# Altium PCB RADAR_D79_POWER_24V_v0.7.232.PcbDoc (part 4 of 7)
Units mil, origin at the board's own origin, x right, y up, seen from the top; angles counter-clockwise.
Board outline 3110.24 x 3110.24 mil, 8 copper layers (Top Layer, GND1, SIG1, PWR1, PWR2, SIG2, GND2, Bottom Layer), stack 55.2 mil thick; 304 components, 269 nets, 1408 pads, 1367 vias.
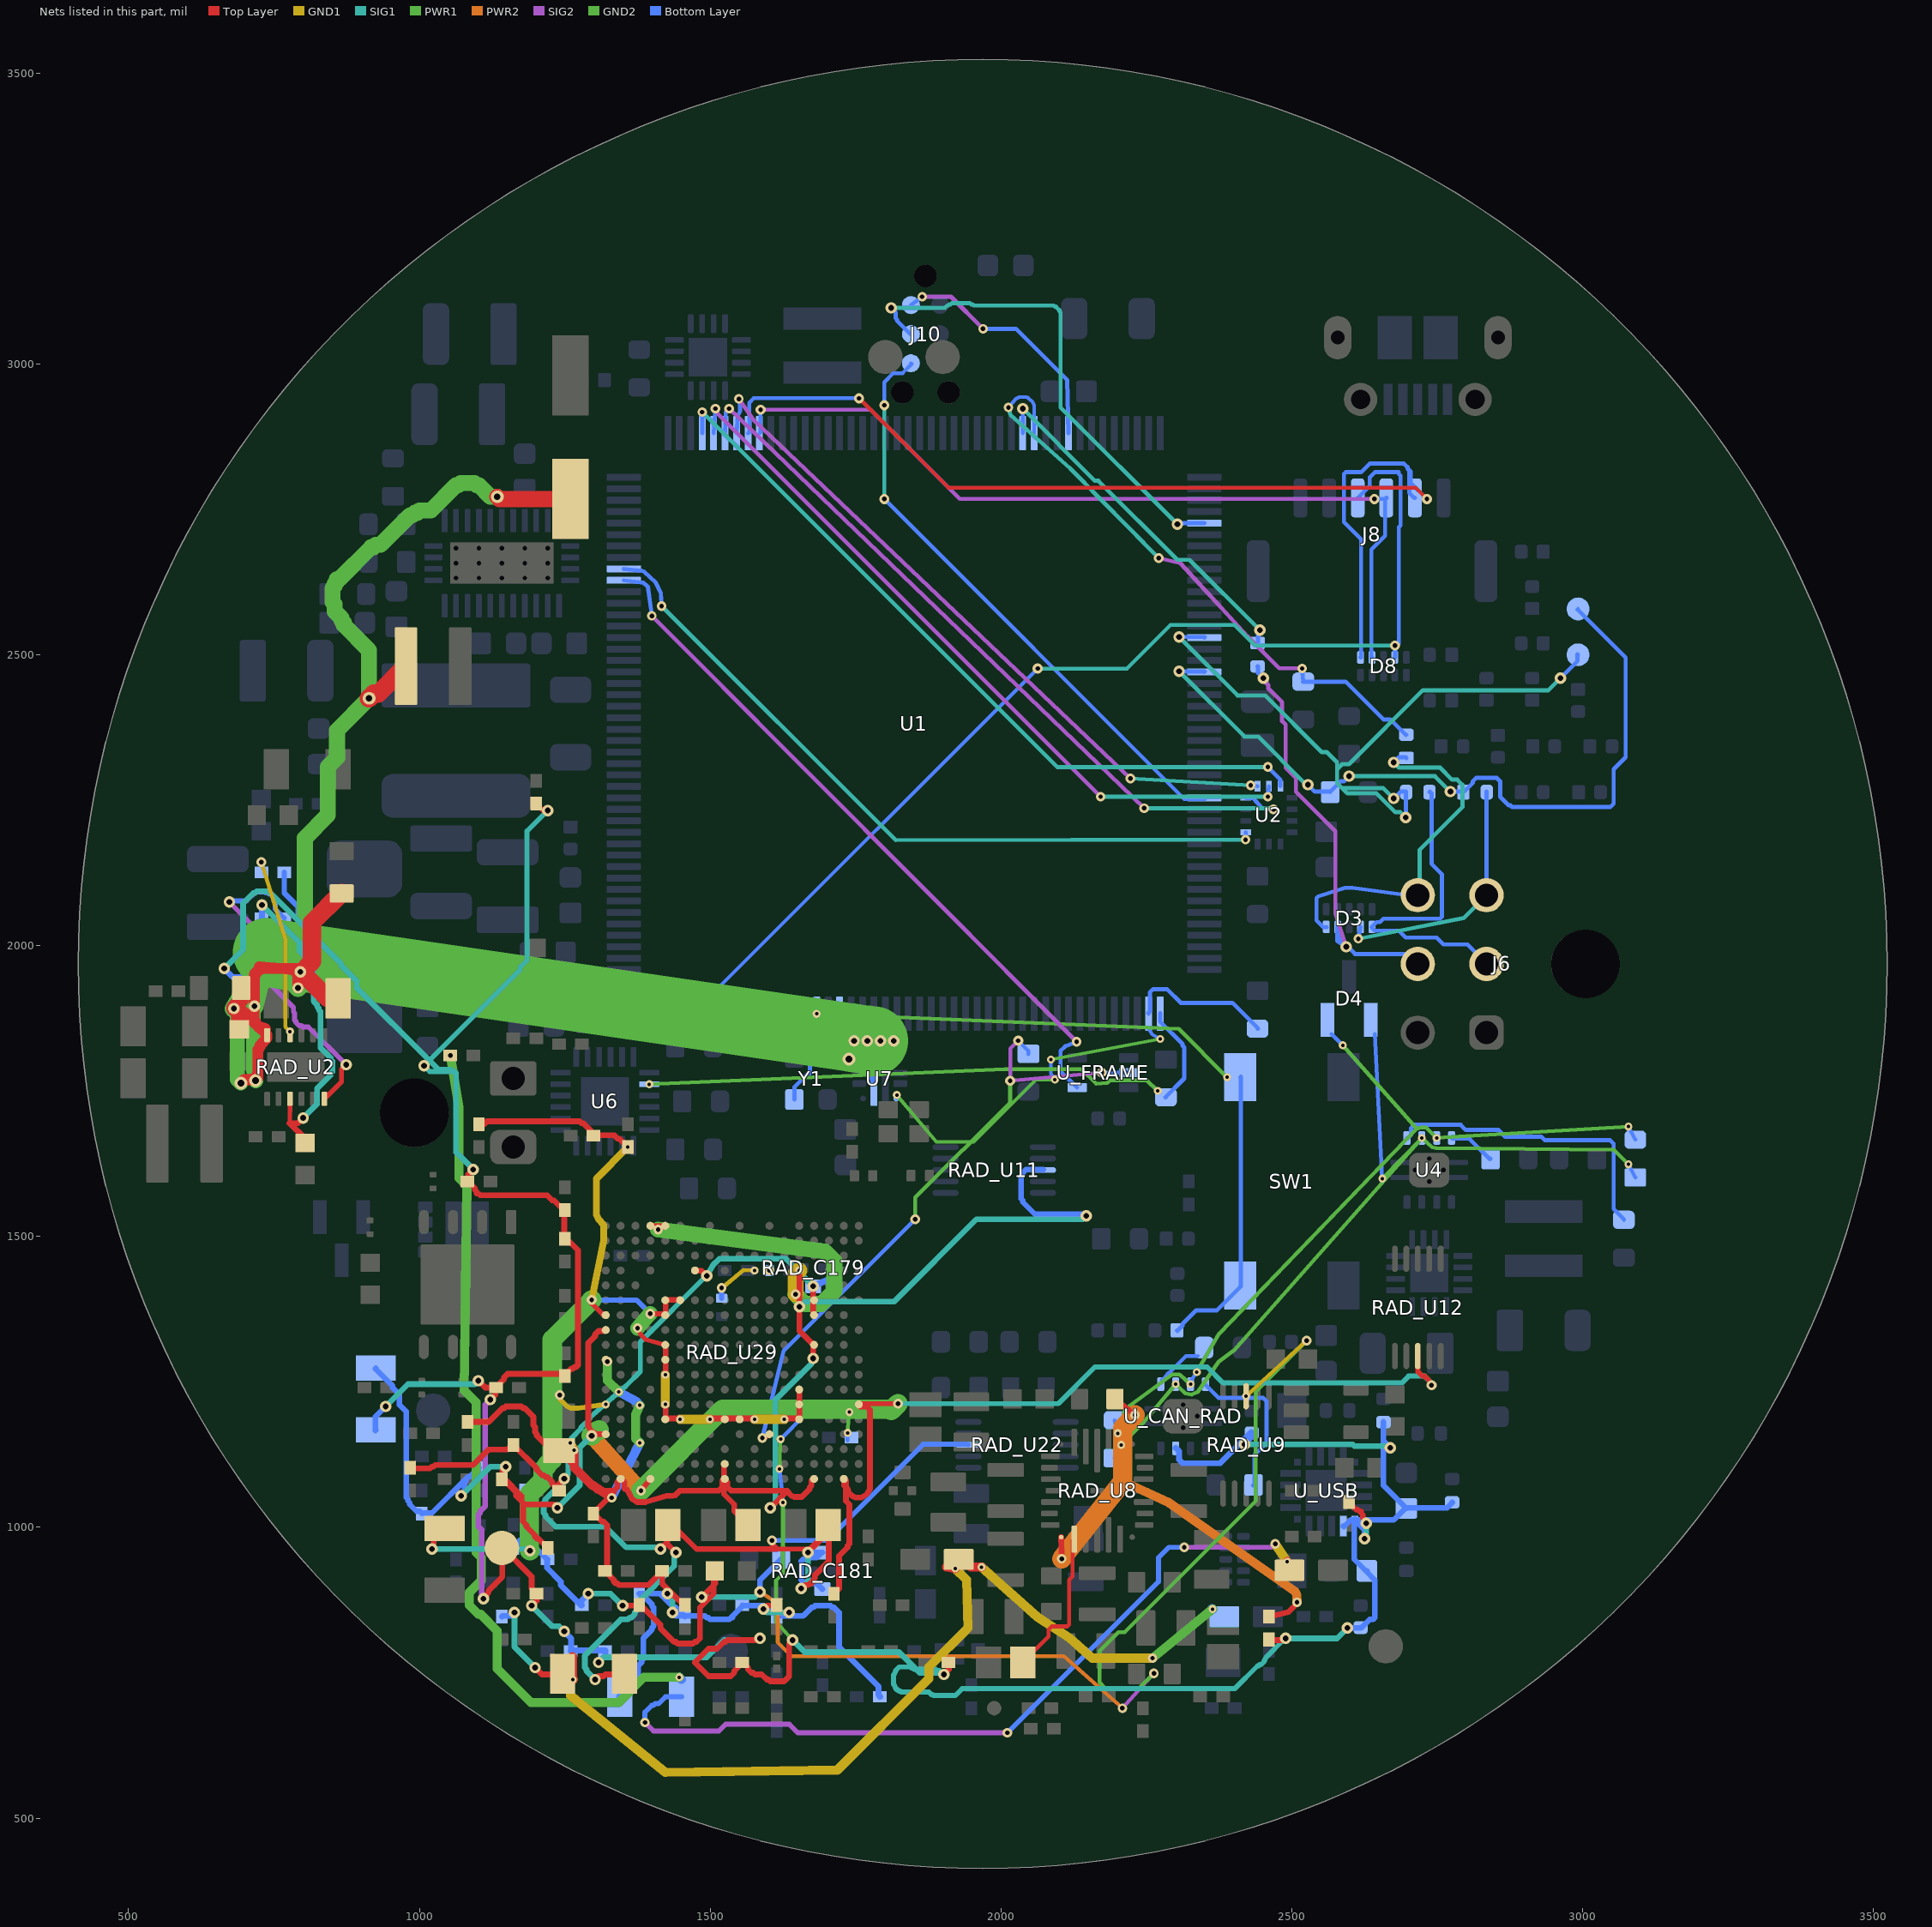
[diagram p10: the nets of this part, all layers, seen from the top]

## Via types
v1: diameter 13.77, hole 5.9, Top Layer to GND1, tented both sides, 393 vias
v2: diameter 16.54, hole 7.87, Top Layer to Bottom Layer, tented both sides, 129 vias
v3: diameter 19.68, hole 9.84, Top Layer to Bottom Layer, tented both sides, 126 vias
v4: diameter 13.77/13.77 (per signal layer), hole 5.9, Top Layer to GND1, tented both sides, 120 vias
v5: diameter 13.77, hole 5.9, Top Layer to GND1, tented top, 104 vias
v6: diameter 13.78, hole 5.91, Top Layer to GND1, tented both sides, 75 vias
v7: diameter 19.68, hole 9.84, Top Layer to Bottom Layer, 74 vias
v8: diameter 17.32, hole 7.87, Top Layer to Bottom Layer, tented both sides, 71 vias
v9: diameter 13.78, hole 5.91, GND2 to Bottom Layer, tented both sides, 64 vias
v10: diameter 13.78, hole 5.91, Top Layer to GND1, tented bottom, 39 vias
v11: diameter 13.78, hole 5.91, GND2 to Bottom Layer, tented top, 38 vias
v12: diameter 13.78, hole 5.91, Top Layer to GND1, 26 vias
v13: diameter 16.54, hole 7.87, GND2 to Bottom Layer, tented both sides, 22 vias
v14: diameter 16.54, hole 7.87, Top Layer to Bottom Layer, 19 vias
v15: diameter 22.05, hole 11.81, Top Layer to Bottom Layer, tented both sides, 17 vias
v16: diameter 13.78, hole 5.91, GND2 to Bottom Layer, 9 vias
v17: diameter 18.11, hole 9.06, Top Layer to Bottom Layer, 7 vias
v18: diameter 22.83, hole 11.81, Top Layer to Bottom Layer, 6 vias
v19: diameter 22.05, hole 11.81, Top Layer to Bottom Layer, 6 vias
v20: diameter 22.83, hole 11.81, Top Layer to Bottom Layer, tented both sides, 5 vias
v21: diameter 19.68, hole 7.87, Top Layer to Bottom Layer, 3 vias
v22: diameter 17.32, hole 8.66, Top Layer to Bottom Layer, 3 vias
v23: diameter 20.47, hole 9.84, Top Layer to Bottom Layer, 3 vias
v24: diameter 17.72, hole 9.84, Top Layer to Bottom Layer, tented both sides, 2 vias
v25: diameter 22.05, hole 11.02, Top Layer to Bottom Layer, 2 vias
v26: diameter 19.68, hole 11.81, Top Layer to Bottom Layer, 2 vias
v27: diameter 18, hole 9.84, Top Layer to Bottom Layer, tented both sides, 1 vias
v28: diameter 18.11, hole 9.06, Top Layer to Bottom Layer, tented both sides, 1 vias

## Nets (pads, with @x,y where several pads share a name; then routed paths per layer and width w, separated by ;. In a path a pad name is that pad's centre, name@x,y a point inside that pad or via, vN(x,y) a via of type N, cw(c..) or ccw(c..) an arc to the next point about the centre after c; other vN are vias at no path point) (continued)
GNSS_PPS: D8.4 J8.4 U1.40 | length 1929.4
  SIG1 w6.69: v8(2062.99,2476.38) 2216.54,2476.38 2291.34,2551.18 2401.57,2551.18 2437.01,2515.75 v8(2677.17,2515.75)
  Bottom Layer w6.69: U1.40@1505.91,1882.87 1507.87,1881.89 1507.87,1921.26 v8(2062.99,2476.38) ; D8.4@2677.17,2495.47 2677.17,2496.06 v8(2677.17,2515.75)
  Bottom Layer w7.09: J8.4@2613.19,2769.68 2633.86,2790.35 2633.86,2805.12 2642.72,2813.98 2684.06,2813.98 2684.06,2811.02 2687.01,2808.07 2687.01,2722.44 2684.06,2719.49 2684.06,2518.7 2678.15,2512.8 2678.15,2495.08 D8.4@2677.17,2495.47
GNSS_RX_EXT: D8.1 J8.2 U1.96 | length 1867.5
  Top Layer w6.69: v8(1755.91,2940.94) 1909.45,2787.4 2712.6,2787.4 v8(2732.28,2767.72)
  Bottom Layer w6.69: U1.96@1564.96,2880.91 1566.93,2881.89 1566.93,2933.07 1574.8,2940.94 v8(1755.91,2940.94) ; 2698.82,2819.88 2700.79,2818.9 2704.72,2814.96 2704.72,2795.28 v8(2732.28,2767.72)
  Bottom Layer w7.09: D8.1@2618.11,2495.47 2619.09,2495.08 2619.09,2698.82 2589.57,2728.35 2589.57,2811.02 2592.52,2813.98 2619.09,2813.98 2633.86,2828.74 2692.91,2828.74 2698.82,2822.83 2698.82,2819.88 2701.77,2816.93 2701.77,2778.54 2710.63,2769.68 J8.2@2711.61,2769.68
GNSS_TX_EXT: D8.2 J8.3 U1.97 | length 1469.8
  SIG2 w6.69: v8(1586.61,2921.26) 1775.59,2921.26 1929.13,2767.72 v8(2641.73,2767.72)
  Bottom Layer w6.69: U1.97@1584.65,2880.91 1586.61,2881.89 v8(1586.61,2921.26) ; v8(2641.73,2767.72) 2661.42,2767.72 J8.3@2662.4,2769.68
  Bottom Layer w7.09: D8.2@2637.8,2495.47 2636.81,2495.08 2636.81,2681.1 2660.43,2704.72 2660.43,2766.73 2661.42,2767.72 2663.39,2769.68 J8.3@2662.4,2769.68
HOST_UART1_RX: R600.2 R602.2 TP2.1 U1.150 | length 1331.2
  SIG1 w7.09: v3(2306.1,2471.46) 2418.31,2359.25 2441.93,2359.25 2521.65,2279.53 2524.61,2279.53 v7(2527.56,2276.57) ; v3(2598.43,2291.34) 2746.06,2291.34 v3(2772.64,2264.76)
  Bottom Layer w7.09: v3(2306.1,2471.46) 2350.39,2471.46 U1.150@2349.41,2470.47 ; v7(2527.56,2276.57) 2539.37,2264.76 R600.2@2565.94,2264.76 ; R600.2@2565.94,2263.78 R600.2@2565.94,2264.76 ; v3(2598.43,2291.34) 2589.57,2282.48 2583.66,2282.48 R600.2@2565.94,2264.76 ; v3(2772.64,2264.76) R602.2@2796.26,2264.76 ; R602.2@2794.88,2263.78 R602.2@2796.26,2264.76 ; TP2.1@2992.13,2578.74 2991.14,2577.76 3073.82,2495.08 3073.82,2323.82 3053.15,2303.15 3053.15,2244.09 3047.24,2238.19 2878.94,2238.19 2875.98,2241.14 2873.03,2241.14 2858.27,2255.91 2858.27,2282.48 2852.36,2288.39 2816.93,2288.39 2811.02,2282.48 2811.02,2279.53 R602.2@2796.26,2264.76
HOST_UART1_RX_EXT: D3.2 J6.3 R602.1 | length 440.1
  SIG1 w7.09: v2(2614.17,2011.81) 2795.28,2047.24 J6.3@2834.65,2086.61
  Bottom Layer w7.09: v2(2614.17,2011.81) D3.2@2618.11,2032.09 ; J6.3@2834.65,2086.61 2834.65,2087.6 2834.65,2264.76 R602.1@2835.04,2263.78
HOST_UART1_TX: R601.2 TP1.1 U1.147 | length 1255.2
  SIG1 w7.09: v3(2306.1,2530.51) 2406.5,2430.12 2453.74,2430.12 2551.18,2332.68 2560.04,2332.68 2577.76,2314.96 2577.76,2303.15 ; v7(2675.2,2252.95) 2657.48,2270.67 2586.61,2270.67 ; v7(2695.87,2220.47) 2687.01,2229.33 2678.15,2229.33 2645.67,2261.81 2595.47,2261.81 2586.61,2270.67 ; v7(2961.61,2459.65) 2940.94,2438.98 2725.39,2438.98 2598.43,2312.01 2586.61,2312.01 2577.76,2303.15 ; 2577.76,2303.15 2577.76,2279.53 2586.61,2270.67
  Bottom Layer w7.09: v3(2306.1,2530.51) 2350.39,2530.51 U1.147@2349.41,2529.53 ; v7(2675.2,2252.95) 2687.01,2264.76 R601.2@2695.87,2264.76 ; v7(2695.87,2220.47) R601.2@2695.87,2264.76 ; R601.2@2696.46,2263.78 R601.2@2695.87,2264.76 ; v7(2961.61,2459.65) 2991.14,2489.17 2991.14,2500.98 TP1.1@2992.13,2500
HOST_UART1_TX_EXT: D3.1 J6.2 R601.1 | length 579.3
  Bottom Layer w7.09: D3.1@2637.8,2032.09 D3.1@2636.81,2031.5 ; R601.1@2736.61,2263.78 2737.2,2264.76 2740.16,2261.81 2740.16,2140.75 2757.87,2123.03 2757.87,2049.21 2754.92,2046.26 2657.48,2046.26 2651.57,2040.35 2645.67,2040.35 2637.6,2032.28 D3.1@2636.81,2031.5 ; J6.2@2834.65,1968.5 2834.65,1969.49 2802.17,2001.97 2760.83,2001.97 2749.02,2013.78 2695.87,2013.78 2684.06,2025.59 2642.72,2025.59 D3.1@2636.81,2031.5
HOST_UART2_RX: R604.2 R605.2 U1.121 | length 1039.6
  SIG1 w7.09: v2(2012.8,2925.2) 2016.14,2912.6 2118.9,2820.47 v2(2271.26,2666.34)
  SIG2 w7.09: v2(2271.26,2666.34) 2308.46,2657.48 2423.62,2531.69 2478.54,2476.77 v2(2517.72,2476.38)
  Bottom Layer w6.3: v2(2012.8,2925.2) 2025.59,2939.96 2031.5,2942.91 2043.31,2942.91 2046.26,2941.93 2054.13,2935.04 2057.09,2929.13 U1.121@2057.09,2880.91
  Bottom Layer w7.09: v2(2517.72,2476.38) R605.2@2519.68,2453.74 ; R604.2@2696.85,2362.6 2695.87,2362.2 2669.29,2388.78 2657.48,2388.78 2592.52,2453.74 R605.2@2519.68,2453.74 ; R605.2@2519.68,2453.74 2518.7,2453.74 R605.2@2519.68,2453.74
HOST_UART2_RX_EXT: D3.5 J6.6 R604.1 | length 624.9
  SIG1 w7.09: v3(2675.2,2314.96) 2684.06,2306.1 2754.92,2306.1 2775.59,2285.43 2784.45,2285.43 2793.31,2276.57 2793.31,2238.19 2719.49,2164.37 2719.49,2090.55 2716.54,2087.6 J6.6@2716.54,2086.61
  Bottom Layer w7.09: D3.5@2559.06,2032.09 2560.04,2031.5 2554.13,2031.5 2542.32,2043.31 2542.32,2081.69 2545.28,2084.65 2591.54,2099.41 2604.33,2099.41 2713.58,2084.65 2716.54,2087.6 J6.6@2716.54,2086.61 ; v3(2675.2,2314.96) 2684.06,2323.82 2695.87,2323.82 R604.1@2696.85,2322.44
HOST_UART2_TX: R603.2 U1.120 | length 634.1
  SIG1 w7.09: v3(2037.4,2923.23) 2161.42,2799.21 2167.32,2799.21 2303.15,2663.39 2323.82,2663.39 v7(2444.88,2542.32)
  Bottom Layer w7.09: U1.120@2037.4,2880.91 2037.4,2881.89 v3(2037.4,2923.23) ; R603.2@2440.94,2520.08 2441.93,2518.7 2441.93,2539.37 v7(2444.88,2542.32)
HOST_UART2_TX_EXT: D3.4 J6.5 R603.1 | length 758.4
  SIG2 w7.09: v7(2450.79,2459.65) 2456.69,2453.74 2456.69,2450.79 2459.65,2447.83 2459.65,2441.93 2483.27,2418.31 2483.27,2385.83 2489.17,2379.92 2489.17,2306.1 2506.89,2288.39 2506.89,2264.76 2574.8,2196.85 2574.8,2055.12 v7(2593.5,1998.03)
  Bottom Layer w7.09: R603.1@2440.94,2479.92 2441.93,2480.32 2441.93,2468.5 v7(2450.79,2459.65) ; D3.4@2578.74,2032.09 D3.4@2577.76,2031.5 ; v7(2593.5,1998.03) 2577.76,2007.87 D3.4@2577.76,2031.5 ; J6.5@2716.54,1968.5 2715.94,1969.09 2699.41,1985.63 2608.46,1985.63 2580.91,2013.19 2580.71,2013.78 2580.71,2028.54 D3.4@2577.76,2031.5
IMU_DRDY: U1.80 U2.4 | length 1289
  SIG1 w7.09: v2(1416.34,2583.66) 1818.9,2181.1 v2(2420.28,2182.09)
  Bottom Layer w7.09: U1.80@1351.38,2647.64 1381.89,2644.68 1386.81,2642.72 1406.5,2624.02 1415.35,2605.32 v2(1416.34,2583.66) ; v2(2420.28,2182.09) U2.4@2420.77,2194.88
IMU_MISO: U1.94 U2.1 | length 1314.4
  SIG1 w7.09: v2(2246.06,2236.22) 2466.54,2236.22 v2(2468.5,2234.25)
  SIG2 w7.09: v2(1532.48,2923.23) v2(2246.06,2236.22)
  Bottom Layer w7.09: U1.94@1525.59,2880.91 1526.57,2917.32 v2(1532.48,2923.23) ; U2.1@2420.77,2253.94 2433.07,2253.94 2448.82,2236.22 v2(2468.5,2234.25)
IMU_MOSI: U1.95 U2.14 | length 1218.4
  SIG1 w7.09: v2(2222.44,2287.4) v2(2429.13,2275.59)
  SIG2 w7.09: v2(1549.21,2939.96) 1574.8,2903.54 v2(2222.44,2287.4)
  Bottom Layer w7.09: U1.95@1545.28,2880.91 1547.24,2911.42 1550.2,2915.35 1551.18,2918.31 1551.18,2937.99 v2(1549.21,2939.96) ; v2(2429.13,2275.59) U2.14@2440.94,2274.11
IMU_NSS: U1.92 U2.12 | length 1303.6
  SIG1 w7.09: v2(1486.22,2917.32) 2096.46,2307.09 v2(2458.66,2307.09)
  Bottom Layer w7.09: U1.92@1486.22,2880.91 v2(1486.22,2917.32) ; v2(2458.66,2307.09) 2480.32,2285.43 U2.12@2480.31,2274.11
IMU_SCK: U1.93 U2.13 | length 1289
  SIG1 w7.09: v2(2171.26,2255.91) v2(2458.66,2255.91)
  SIG2 w7.09: v2(1508.86,2923.23) 1513.78,2913.39 v2(2171.26,2255.91)
  Bottom Layer w7.09: U1.93@1505.91,2880.91 v2(1508.86,2923.23) ; v2(2458.66,2255.91) U2.13@2460.63,2274.11
MCU_HSE_25M: U1.29 Y1.3 | length 204.3
  Bottom Layer w7.09: Y1.3@1644.68,1735.24 1644.68,1756.89 1668.31,1780.51 1671.26,1780.51 1671.26,1830.71 1683.07,1842.52 1718.5,1842.52 1718.5,1845.47 1721.46,1848.43 1721.46,1883.86 U1.29@1722.44,1882.87
NRST: C115.1 SW1.1 U1.31 | length 1247.5
  GND2 w6.69: v11(1683.07,1882.87) 2305.51,1856.69 v11(2388.58,1773.62)
  Bottom Layer w7.09: C115.1@2302.36,1338.58 2303.15,1337.6 2312.01,1346.46 2312.01,1349.41 2335.63,1373.03 2371.06,1373.03 SW1.1@2412.4,1414.37 ; SW1.1@2411.42,1415.35 SW1.1@2412.4,1414.37 ; SW1.1@2411.42,1773.62 2412.4,1774.61 SW1.1@2412.4,1414.37
RAD_CAN_SHDN: R_CAN_SHDN.1 U_CAN_RAD.5 | length 81.7
  Bottom Layer w6.3: U_CAN_RAD.5@2276.18,1253.35 2276.08,1253.69 2277.31,1253.69 2285.93,1262.3 2285.93,1263.53 2287.16,1263.53 2287.16,1264.76 2288.39,1264.76 2288.39,1265.99 2289.62,1265.99 2317.91,1294.29 2337.6,1294.29 R_CAN_SHDN.1@2338.19,1294.88
RAD_CAN_STB: R_CAN_STB.1 U_CAN_RAD.8 | length 275.4
  Bottom Layer w7.09: U_CAN_RAD.8@2351.38,1246.06 2350.39,1246.06 2350.89,1245.57 2374.02,1222.44 2450.79,1222.44 2456.69,1216.54 2456.69,1145.67 2436.02,1125 2436.02,1074.8 R_CAN_STB.1@2434.06,1072.83 ; R_CAN_STB.1@2434.06,1072.83 2433.07,1071.85 R_CAN_STB.1@2434.06,1072.83
RAD_FRAME_RAW: R_FRAME_PD.1 RAD_U29.G15 U_FRAME.2 | length 1106.1
  Top Layer w7.09: v2(1589.57,1153.54) 1590.55,1154.53 1595.47,1154.53 1601.38,1160.43 RAD_U29.G15@1601.8,1160.03
  PWR1 w7.09: v2(1852.36,1529.53) 1852.36,1566.93 2015.75,1730.32 v8(2015.75,1767.72)
  SIG2 w6.69: v8(2015.75,1767.72) 2015.75,1822.83 v8(2029.53,1836.61)
  SIG2 w7.09: v8(2015.75,1767.72) v2(2173.03,1781.69)
  Bottom Layer w6.69: v8(2029.53,1836.61) 2047.24,1818.9 R_FRAME_PD.1@2047.24,1813.98 ; R_FRAME_PD.1@2047.24,1813.98 2047.24,1812.99 R_FRAME_PD.1@2047.24,1813.98
  Bottom Layer w7.09: v2(1589.57,1153.54) 1625.98,1303.15 v2(1852.36,1529.53) ; v2(2173.03,1781.69) U_FRAME.2@2219.49,1781.5
RADAR_12V: RAD_C99.1 RAD_C101.1 RAD_C118.2 RAD_C173.2 RAD_C195.1 RAD_L5.2 RAD_R7.1 RAD_U2.12 U7.6 | length 4553.2
  Top Layer w12.2: v3@716.54,1897.64 v3(716.54,1895.67) 716.54,1872.05 716.54,1871.06 716.54,1870.08 717.88,1868.73 718.5,1868.11 727.36,1859.25 730.32,1856.3 740.16,1846.46 738.18,1846.43 RAD_U2.12@737.32,1846.42
  Top Layer w18.9: v3(681.1,1891.73) 682.09,1890.75 684.06,1890.75 692.91,1890.75 717.52,1866.14 ; v15(692.91,1763.78) 698.82,1769.68 710.63,1769.68 712.6,1770.47 716.54,1770.47 720.47,1775.59 721.42,1779.53 722.44,1781.5 ; 716.54,1871.06 715.55,1872.05 715.55,1946.85 716.54,1947.83 716.54,1950.79 717.52,1951.77 717.52,1952.76 723.43,1958.66 724.23,1958.66 ; 716.54,1872.05 717.56,1870.08 717.88,1868.73 ; v3@716.54,1897.64 716.54,1946.85 717.56,1948.82 718.5,1952.76 722.44,1956.69 724.08,1957.03 724.23,1958.66 ; v15(718.5,1767.72) 722.44,1771.65 722.44,1781.5 ; RAD_U2.12@734.84,1856.69 RAD_U2.12@735.24,1856.3 ; v3(791.34,1927.17) 791.34,1946.85 790.55,1948.82 790.55,1952.76 785.43,1956.69 783.8,1957.03 781.83,1959 761.89,1960.63 ; v3(795.28,1954.72) 789.37,1960.63 761.89,1960.63 ; 717.52,1866.14 723.43,1860.24 ; 717.52,1866.14 717.52,1867.13 716.54,1868.11 716.54,1870.08 717.88,1868.73 ; 717.88,1868.73 718.5,1868.11 718.5,1866.14 ; 717.88,1868.73 718.5,1866.14 ; 718.5,1866.14 724.25,1860.24 ; 722.44,1781.5 722.44,1820.87 724.41,1822.83 724.41,1824.8 726.38,1826.77 726.38,1828.74 737.32,1840.91 737.32,1846.06 737.32,1846.42 737.32,1846.82 728.09,1856.3 ; 723.43,1860.24 727.36,1856.3 728.09,1856.3 ; 723.43,1860.24 724.25,1860.24 ; 724.25,1860.24 728.09,1856.3 ; 724.25,1860.24 724.41,1860.24 725.39,1859.25 727.36,1859.25 728.35,1859.25 729.33,1858.27 733.27,1858.27 RAD_U2.12@735.24,1856.3 ; 724.23,1958.66 724.71,1963.68 761.89,1960.63 ; 724.23,1958.66 724.41,1958.66 725.39,1959.65 728.35,1959.65 729.33,1960.63 761.89,1960.63 ; 728.09,1856.3 730.32,1856.3 RAD_U2.12@735.24,1856.3
  Top Layer w25.59: v3(681.1,1891.73) v3@681.1,1893.7 ; RAD_C195.1@690.2,1856.13 688.98,1854.33 688.98,1885.83 684.06,1890.75 v3@681.1,1893.7 ; RAD_C118.2@693.77,1927.05 692.91,1925.2 692.91,1905.51 v3@681.1,1893.7
  Top Layer w27.56: v25(1133.86,2771.65) 1137.8,2767.72 RAD_C99.1@1259.84,2767.72
  Top Layer w31.5: v3(795.28,1954.72) v3@796.18,1952.76 ; RAD_C101.1@860.24,1909.45 842.52,1909.45 799.21,1952.76 v3@796.18,1952.76 ; RAD_C173.2@866.14,2089.57 866.14,2090.55 814.96,2039.37 814.96,1972.44 796.73,1953.33 v3@796.18,1952.76 ; v25(913.39,2425.2) 921.26,2433.07 929.13,2433.07 976.38,2480.32 RAD_L5.2@976.97,2480.32
  PWR1 w25.59: v3(681.1,1891.73) 683.07,1889.76 683.07,1885.83 687.01,1881.89 687.01,1769.68 v15(692.91,1763.78) ; v3(716.54,1895.67) 714.57,1893.7 714.57,1785.43 716.54,1783.46 716.54,1777.56 718.5,1775.59 v15(718.5,1767.72) ; v19(1738.19,1805.12) 1738.19,1826.77 1747.64,1836.22 1748.03,1836.61 v3(1747.24,1836.22)
  PWR1 w27.56: v3@795.28,1952.76 v3(795.28,1954.72) 795.28,1968.5 803.15,1976.38 803.15,1978.73 803.15,2185.04 842.52,2224.41 842.52,2307.09 858.27,2322.83 858.27,2370.08 v25(913.39,2425.2) 913.39,2507.87 870.08,2551.18 870.08,2555.12 866.14,2559.06 866.14,2562.99 854.33,2574.8 854.33,2586.61 850.39,2590.55 850.39,2614.17 854.33,2618.11 854.33,2622.05 858.27,2625.98 858.27,2629.92 862.2,2629.92 917.32,2685.04 921.26,2685.04 925.2,2688.98 933.07,2688.98 984.25,2740.16 988.19,2740.16 992.13,2744.09 996.06,2744.09 1000,2748.03 1019.68,2748.03 1062.99,2791.34 1066.93,2791.34 1070.87,2795.28 1094.49,2795.28 1098.43,2791.34 1102.36,2791.34 1122.05,2771.65 v25(1133.86,2771.65)
  PWR1 w31.5: v3(681.1,1891.73) 738.19,1988.19 ; v3(716.54,1895.67) 738.19,1988.19 ; v3(791.34,1927.17) 779.39,1940.89 738.19,1988.19 ; v3(795.28,1954.72) 738.19,1988.19
  PWR1 w39.37: v3(1747.24,1836.22) 1747.64,1836.22 v3(1770.08,1836.22) 1781.5,1836.22 v3(1792.91,1836.22) v3(1815.75,1836.22)
  PWR1 w118.11: 738.19,1988.19 798.86,1979.35 798.94,1979.34 803.15,1978.73 1743.53,1841.75 1747.96,1841.11 1770.32,1837.85 1781.5,1836.22
  Bottom Layer w9.45: RAD_R7.1@767.72,2125.98 767.72,2090.55 791.34,2066.93 791.34,1956.69 795.28,1952.76 v3(795.28,1954.72)
  Bottom Layer w10.24: U7.6@1781.5,1807.87 1781.5,1814.96 1781.5,1822.83 1781.5,1824.8 1781.5,1836.22
  Bottom Layer w15.75: v19(1738.19,1805.12) 1744.09,1811.02 1744.09,1814.96 1746.06,1816.93 1746.06,1818.9 1750,1822.83 1751.97,1822.83 1753.94,1824.8 1759.84,1824.8 ; v3(1747.24,1836.22) 1748.03,1836.61 1748.43,1836.22 1759.25,1825.39 1759.84,1824.8 ; v3@1769.68,1836.61 v3(1770.08,1836.22) 1781.5,1824.8 1783.46,1826.77 ; U7.6@1781.5,1771.65 U7.6@1781.5,1807.87 ; U7.6@1781.5,1814.96 1779.53,1816.93 1779.53,1818.9 1775.59,1822.83 1773.62,1822.83 1771.65,1824.8 1770.08,1824.8 1759.84,1824.8 ; 1781.5,1822.83 1783.13,1825.14 1783.46,1826.77 ; v3@1793.31,1836.61 v3(1792.91,1836.22) v3@1788.78,1832.09 ; v3(1815.75,1836.22) 1814.96,1836.61 1814.57,1836.22 1811.02,1832.68 1791.34,1832.68 1789.37,1832.09 v3@1788.78,1832.09 ; 1783.46,1826.77 v3@1788.78,1832.09 ; 1783.46,1826.77 1787.4,1832.09 v3@1788.78,1832.09
  Bottom Layer w18.5: v3(1747.24,1836.22) 1748.43,1836.22 v3(1770.08,1836.22) 1781.5,1836.22 v3(1792.91,1836.22) 1814.57,1836.22 v3(1815.75,1836.22)
RADAR_CANH: D4.1 R40.1 R_CAN_TERM.1 U4.7 U_CAN_RAD.7 | length 1404.4
  GND2 w6.69: v9(2200.79,1161.42) 2212.6,1200.79 2216.54,1205.71 2294.29,1262.8 2306.1,1262.8 2308.07,1261.81 v11(2325.79,1246.06) ; v9(2336.61,1266.73) 2375,1332.68 2714.57,1685.04 ; v9(2587.6,1828.74) 2714.57,1685.04 ; v9(3078.74,1688.98) v11(2749.02,1669.29) 2731.3,1687.01 2721.46,1687.01 2714.57,1685.04
  Bottom Layer w6.69: R_CAN_TERM.1@2194.88,1184.06 v9(2200.79,1161.42) ; U_CAN_RAD.7@2327.17,1253.15 v9(2336.61,1266.73) ; D4.1@2568.11,1848.23 v9(2587.6,1828.74) ; v9(3078.74,1688.98) R40.1@3090.55,1666.34
RADAR_CANL: D4.2 R40.2 R_CAN_TERM.2 U4.6 U_CAN_RAD.6 | length 1538.3
  GND2 w6.69: v9(2206.69,1141.73) 2244.09,1179.13 v11(2300.2,1246.06) 2316.93,1230.32 2327.76,1228.35 2337.6,1232.28 2374.02,1284.45 2400.59,1304.13 2658.95,1596.37 v11(2723.43,1669.29) ; v9(2655.51,1599.41) v11(2723.43,1669.29) ; v9(3078.74,1624.02) 3054.13,1648.62 2748.03,1651.57 2741.14,1653.54 v11(2723.43,1669.29)
  Bottom Layer w6.69: R_CAN_TERM.2@2194.88,1119.09 v9(2206.69,1141.73) ; D4.2@2642.91,1848.23 v9(2655.51,1599.41) ; v9(3078.74,1624.02) R40.2@3090.55,1601.38
RADAR_EFUSE_FLT: R7F.1 U1.2 U7.4 | length 871.5
  GND2 w6: v9(1820.87,1743.11) 1888.78,1662.4 1952.76,1662.4 2060.04,1769.68 v9(2092.52,1769.68) ; v9(2085.63,1804.13) v9(2273.62,1839.57)
  Bottom Layer w6: U7.4@1820.08,1737.4 v9(1820.87,1743.11) ; v9(2085.63,1804.13) 2085.63,1780.51 v9(2092.52,1769.68) ; U1.2@2252.76,1858.07 2259.84,1847.44 v9(2273.62,1839.57)
  Bottom Layer w7.09: U1.2@2253.94,1882.87 2252.95,1883.86 2255.91,1886.81 2255.91,1919.29 2261.81,1925.2 2285.43,1925.2 2309.06,1901.57 2397.64,1901.57 2441.93,1857.28 R7F.1@2440.94,1857.28
RADAR_REF: U1.79 U_FRAME.4 | length 1236.5
  SIG2 w7.09: v2(1399.61,2566.93) v2(2129.92,1834.65)
  Bottom Layer w7.09: U1.79@1351.38,2627.95 1384.84,2624.02 1392.72,2617.13 v2(1399.61,2566.93) ; v2(2129.92,1834.65) 2110.24,1826.77 2102.36,1818.9 2102.36,1783.46 U_FRAME.4@2130.91,1755.91
SHDN_PD: R42.1 U4.5 | length 525.9
  Bottom Layer w7.09: U4.5@2697.83,1669.29 2698.82,1668.31 2704.72,1674.21 2704.72,1686.02 2707.68,1688.98 2707.68,1691.93 2790.35,1691.93 2799.21,1683.07 2855.32,1683.07 2867.13,1671.26 2929.13,1671.26 2935.04,1665.35 3047.24,1665.35 3053.15,1659.45 3053.15,1547.24 3070.87,1529.53 R42.1@3070.87,1528.54
STB_PD: R41.1 U4.8 | length 82.4
  Bottom Layer w7.09: U4.8@2774.61,1669.29 2775.59,1668.31 2805.12,1668.31 2840.55,1632.87 R41.1@2841.54,1633.86
SWCLK: J10.4 U1.137 | length 856.4
  SIG1 w7.09: v3(1811.02,3096.46) 1903.54,3096.46 1907.48,3100.39 1909.45,3100.39 1911.42,3102.36 1913.39,3102.36 1915.35,3104.33 1946.85,3104.33 1948.82,3102.36 1950.79,3102.36 1952.76,3100.39 2090.55,3100.39 2092.52,3098.43 2094.49,3098.43 2100.39,3092.52 2100.39,3090.55 2102.36,3088.58 2102.36,2925.2 v3(2303.15,2724.41)
  Bottom Layer w7.09: v3(1811.02,3096.46) 1818.9,3088.58 1818.9,3078.74 1820.87,3076.77 1820.87,3074.8 1844.49,3051.18 J10.4@1845.08,3051.18 ; v3(2303.15,2724.41) 2305.12,2726.38 U1.137@2349.41,2726.38
SWDIO: J10.2 U1.124 | length 424.2
  SIG2 w7.09: v2(1864.37,3115.55) 1913.98,3115.55 v2(1969.09,3060.43)
  Bottom Layer w7.09: J10.2@1845.08,3101.18 v2(1864.37,3115.55) ; v2(1969.09,3060.43) 2025.59,3060.43 2113.78,2972.24 U1.124@2116.14,2880.91
SWO: J10.6 U1.161 | length 1029.9
  SIG1 w6.69: v8(1799.21,2767.72) v8(1799.21,2929.13)
  Bottom Layer w6.69: v8(1799.21,2767.72) 2314.96,2251.97 2350.39,2251.97 U1.161@2349.41,2253.94 ; v8(1799.21,2929.13) 1799.21,2968.5 1814.96,2984.25 1830.71,2984.25 1846.46,3000 J10.6@1845.08,3001.18
SYS_EFUSE_FLT: R6F.1 U1.1 U6.14 | length 1070.9
  GND2 w6.69: v11(1395.18,1761.61) 2006.3,1787.4 2138.58,1787.4 2163.78,1762.2 2182.68,1763.78 2187.4,1768.5 2250.39,1768.5 v11(2269.49,1750.2)
  Bottom Layer w7.09: U1.1@2273.62,1883.86 U1.1@2273.62,1882.87 2273.62,1869.09 2312.01,1830.71 2312.01,1827.76 2314.96,1824.8 2314.96,1771.65 2282.48,1739.17 R6F.1@2283.46,1739.17
TI_1V0: RAD_C114.1 RAD_C115.2 RAD_C116.1 RAD_C117.2 RAD_C179.1 RAD_C179.3 RAD_C181.1 RAD_C181.3 RAD_R56.1 RAD_R64.2 RAD_U22.8 RAD_U29.D6 RAD_U29.D7 RAD_U29.M4 | length 3051.2
  Top Layer w8.66: v8(1606.3,977.36) 1606.3,971.46 1615.16,962.6 1668.31,962.6 1671.26,962.6 1674.21,965.55 1700.79,992.13 1703.74,995.08 RAD_C114.1@1703.74,1003.94
  Top Layer w9.84: RAD_R56.1@984.25,1102.36 983.27,1101.38 1018.7,1101.38 1021.65,1104.33 1024.61,1104.33 1027.56,1107.28 1092.52,1107.28 1119.09,1133.86 1151.57,1133.86 RAD_C117.2@1160.43,1142.72 ; v3(1249.02,1083.66) 1240.16,1074.8 RAD_C115.2@1240.16,1062.99 1228.35,1074.8 1228.35,1077.76 1219.49,1086.61 1216.54,1086.61 1213.58,1089.57 1210.63,1089.57 1201.77,1098.43 1201.77,1101.38 RAD_C117.2@1161.42,1141.73 ; v3(1302.17,738.19) 1308.07,744.09 1316.93,744.09 1319.88,747.05 1352.36,747.05 RAD_R64.2@1352.36,748.03 ; v3(1414.37,962.6) 1426.18,974.41 ; v3(1440.94,956.69) 1426.18,971.46 1426.18,974.41 ; RAD_U29.M4@1473.85,1441.52 1473.43,1440.94 1485.24,1440.94 v3(1494.09,1432.09) ; 1615.16,962.6 1476.38,962.6 1435.04,1003.94 RAD_C116.1@1427.17,1003.94 1426.18,1003.94 1426.18,974.41 ; v7(1656.5,894.68) 1662.4,900.59 1668.31,900.59 1671.26,903.54 1674.21,903.54 1677.17,906.5 1677.17,909.45 1680.12,912.4 1680.12,918.31 1703.74,941.93 RAD_C114.1@1703.74,995.08 ; 1674.21,965.55 1677.17,965.55 1700.79,989.17 1700.79,992.13 1700.79,1000.98 1703.25,1003.44 1703.74,1003.94 RAD_C114.1@1702.76,1003.94 ; v3(1677.17,1414.37) RAD_U29.D6@1677.17,1390.75 ; RAD_U29.D7@1678.57,1364.75 1677.17,1364.17 1677.17,1390.34 RAD_U29.D6@1677.17,1390.75 ; RAD_U29.D6@1678.57,1390.34 RAD_U29.D6@1677.17,1390.75 ; RAD_C117.2@1160.43,1142.72 RAD_C117.2@1161.42,1141.73 ; RAD_C117.2@1160.43,1142.72 RAD_C117.2@1161.42,1141.73
  SIG1 w8.66: v3(1249.02,1083.66) 1250,1082.68 1253.94,1086.61 1253.94,1088.58 1255.91,1090.55 1255.91,1141.73 1261.81,1147.64 1261.81,1153.54 1277.56,1169.29 1277.56,1171.26 1293.31,1187.01 1293.31,1188.98 1355.32,1243.11 1379.92,1267.72 1379.92,1318.9 1493.6,1432.58 1494.09,1433.07 v3(1494.09,1432.09)
  SIG1 w9.84: v3(1249.02,1083.66) 1249.02,1080.71 1216.54,1048.23 1216.54,1045.28 1213.58,1042.32 1213.58,1024.61 1216.54,1021.65 1216.54,1018.7 1234.25,1000.98 1319.88,1000.98 1355.32,965.55 1411.42,965.55 v3(1414.37,962.6) ; v3(1302.17,738.19) 1287.4,752.95 1287.4,755.91 1284.45,758.86 1284.45,779.53 1346.46,841.54 1358.27,841.54 1361.22,844.49 1364.17,844.49 1370.08,850.39 1370.08,853.35 1373.03,856.3 1373.03,868.11 1437.99,933.07 1437.99,953.74 v3(1440.94,956.69) ; v3(1494.09,1432.09) 1504.92,1450.79 1515.75,1461.61 1629.92,1461.61 1659.45,1432.09 v3(1677.17,1414.37) ; v7(1656.5,894.68) 1668.31,906.5 v7(1668.31,956.69)
  Bottom Layer w8.66: v8(1606.3,977.36) 1700.79,977.36 1866.14,1142.72 1942.91,1142.72 RAD_U22.8@1943.9,1141.73
  Bottom Layer w9.84: v7(1668.31,956.69) RAD_C181.1@1691.93,956.69 ; RAD_C181.3@1692.91,893.7 1691.93,894.68 1683.07,903.54 1662.4,903.54 1656.5,909.45 1656.5,941.93 1659.45,944.88 1662.4,944.88 1665.35,947.83 1683.07,947.83 RAD_C181.1@1691.93,956.69 ; RAD_C181.1@1692.91,956.69 RAD_C181.1@1691.93,956.69
  Bottom Layer w11.81: v3(1677.17,1414.37) 1705.22,1426.67 1711.12,1431.59 1713.09,1436.02 1713.09,1455.71 1712.11,1458.17 1707.18,1464.07 RAD_C179.3@1677.17,1477.36
TI_1V0_FILTERED: RAD_R64.1 RAD_R66.1 RAD_R73.2 RAD_R111.2 | length 1726.6
  Top Layer w9.84: v7(1198.82,758.86) 1210.63,747.05 1246.06,747.05 RAD_R64.1@1246.06,748.03
  Top Layer w15.75: RAD_R64.1@1262.99,777.76 1263.58,748.38 v10(1263.78,738.19) ; RAD_R111.2@1906.3,931.5 v10(1921.26,929.13) ; RAD_R111.2@1948.03,931.5 v6(1966.54,931.59)
  GND1 w15.75: v10(1263.78,738.19) 1259.84,734.25 1259.84,710.63 1423.23,578.74 1718.5,582.68 1875.98,740.16 1875.98,759.84 1942.91,826.77 1940.94,909.45 v10(1921.26,929.13) ; v6(1966.54,931.59) 2062.5,845.96 2118.6,809.06 2156.99,775.1 v2(2260.33,775.1)
  SIG1 w9.84: v7(1163.39,853.35) 1163.39,794.29 v7(1198.82,758.86)
  GND2 w15.75: v2(2260.33,775.1) v11(2363.68,859.25)
  Bottom Layer w9.84: RAD_R66.1@1141.73,846.46 1142.72,847.44 1157.48,847.44 v7(1163.39,853.35)
  Bottom Layer w15.75: RAD_R73.2@2362.99,859.84 v11(2363.68,859.25)
TI_1V2: RAD_C92.2 RAD_C96.2 RAD_C137.2 RAD_C138.2 RAD_C139.2 RAD_C140.2 RAD_C141.2 RAD_C142.2 RAD_C146.2 RAD_R26.1 RAD_R30.2 RAD_U9.8 RAD_U29.E12 RAD_U29.E13 RAD_U29.E14 RAD_U29.F14 RAD_U29.H14 RAD_U29.J14 RAD_U29.K14 RAD_U29.L14 RAD_U29.N6 RAD_U29.N14 RAD_U29.P6 RAD_U29.P7 RAD_U29.P9 RAD_U29.P10 RAD_U29.P11 RAD_U29.P13 RAD_U29.P14 RAD_U29.V7 RAD_U29.V13 | length 4840.6
  Top Layer w7.87: v2(1375,1342.52) 1380.91,1330.71 1388.78,1322.83 RAD_U29.P9@1422.67,1313.57
  Top Layer w8.66: v8(1296.26,1390.75) 1296.26,1384.84 1316.93,1364.17 1319.88,1364.17 RAD_U29.V7@1320.3,1364.75 ; v8(1396.65,1367.13) 1420.28,1367.13 RAD_U29.P7@1422.66,1364.74 ; RAD_U29.P7@1422.66,1364.74 1423.23,1364.17 RAD_U29.P7@1422.67,1364.75
  Top Layer w9.84: v3(1021.65,962.6) 1024.61,965.55 1024.61,980.32 1042.32,998.03 RAD_R30.2@1043.31,998.03 ; RAD_R26.1@1102.36,1692.91 1101.38,1691.93 1110.24,1691.93 1116.14,1697.83 1275.59,1697.83 1278.54,1694.88 1281.5,1694.88 1296.26,1680.12 1296.26,1677.17 RAD_C139.2@1299.21,1674.21 ; RAD_C139.2@1299.21,1673.23 RAD_C139.2@1299.21,1674.21 ; v7(1349.41,865.16) RAD_C96.2@1378.94,865.16 ; v10(1358.27,1653.54) 1343.5,1668.31 1340.55,1668.31 1334.65,1674.21 RAD_C139.2@1299.21,1674.21 ; RAD_C96.2@1377.95,866.14 RAD_C96.2@1378.94,865.16 ; RAD_U29.P14@1422.67,1185.62 RAD_U29.P14@1423.23,1187.01 ; v10(1422.67,1211.21) 1423.23,1210.63 RAD_U29.P14@1423.23,1187.01 ; v10(1422.67,1262.39) 1423.23,1263.78 RAD_U29.P10@1423.23,1287.4 ; RAD_U29.P10@1422.67,1287.98 RAD_U29.P10@1423.23,1287.4 ; RAD_U29.P9@1422.67,1313.57 1423.23,1313.98 RAD_U29.P10@1423.23,1287.4 ; RAD_U29.P6@1422.67,1390.34 RAD_U29.P6@1423.23,1390.75 ; RAD_U29.P7@1423.23,1364.17 RAD_U29.P6@1423.23,1390.75 ; v10(1448.26,1185.62) 1446.85,1187.01 RAD_U29.P14@1423.23,1187.01 ; RAD_U29.N6@1448.26,1390.34 1446.85,1390.75 RAD_U29.P6@1423.23,1390.75 ; v7(1485.24,879.92) 1505.91,900.59 ; v10(1499.44,1185.62) 1500,1187.01 RAD_U29.K14@1523.62,1187.01 ; RAD_C146.2@1507.87,925.2 RAD_C146.2@1508.86,924.21 ; RAD_U29.K14@1525.03,1185.62 RAD_U29.K14@1523.62,1187.01 ; RAD_U29.J14@1550.62,1185.62 RAD_U29.J14@1550.2,1187.01 ; v10(1576.21,1185.62) 1576.77,1187.01 RAD_U29.J14@1550.2,1187.01 ; v10(1627.39,1185.62) 1626.97,1187.01 RAD_U29.E14@1653.54,1187.01 ; RAD_U29.E14@1652.98,1185.62 RAD_U29.E14@1653.54,1187.01 ; RAD_U29.E13@1652.98,1211.21 RAD_U29.E13@1653.54,1210.63 ; RAD_U29.E12@1652.98,1236.8 1653.54,1237.2 RAD_U29.E13@1653.54,1210.63 ; RAD_C96.2@1378.94,865.16 1381.89,865.16 1414.37,832.68 1414.37,826.77 1437.99,803.15 1440.94,803.15 1443.9,800.2 1470.47,800.2 1473.43,803.15 1476.38,803.15 1482.28,809.06 1482.28,862.2 1492.62,872.54 1505.91,885.83 1505.91,900.59 ; 1505.91,900.59 1508.86,903.54 RAD_C146.2@1508.86,924.21 ; 1505.91,900.59 1505.91,921.26 RAD_C146.2@1508.86,924.21 ; RAD_U29.K14@1523.62,1187.01 RAD_U29.J14@1550.2,1187.01 ; RAD_U29.E14@1653.54,1187.01 RAD_U29.E13@1653.54,1210.63
  PWR1 w6.69: v2(2262.8,749.02) 2237.2,723.43 2179.13,723.43 2169.29,733.27 2169.29,787.4 2201.77,819.88 2212.6,819.88 2437.99,1045.28 2437.99,1233.27 v2(2525.59,1320.87)
  PWR1 w15.75: 1228.35,1219.49 v14(1241.14,1227.36)
  PWR1 w25.59: v2(1375,1342.52) v8(1396.65,1367.13)
  PWR1 w33.46: v7(1189.96,959.65) 1188.98,960.63 1188.98,1057.09 1212.6,1080.71 1212.6,1098.43 1218.5,1104.33 1218.5,1106.3 1228.35,1116.14 1228.35,1219.49 1228.35,1322.83 1295.28,1389.76 v8(1296.26,1390.75)
  PWR2 w6.69: v7(1585.63,888.78) 1601.38,878.94 1616.14,864.17 1616.14,802.17 1639.76,778.54 2108.27,778.54 v2(2208.66,688.98)
  GND1 w6.69: v6(2421.26,1225.39) v2(2525.59,1320.87)
  GND1 w8.66: v14(1241.14,1227.36) 1242.13,1219.49 1253.94,1207.68 1259.84,1204.72 1273.62,1204.72 v10(1320.3,1211.21)
  GND1 w11.81: v8(1296.26,1390.75) 1316.93,1493.11 1316.93,1519.68 1308.07,1529.53 1304.13,1537.4 1304.13,1599.41 v10(1358.27,1653.54)
  GND1 w15.75: v10(1422.67,1211.21) v10(1422.67,1262.39) ; v10(1448.26,1185.62) v10(1499.44,1185.62) ; v10(1576.21,1185.62) v10(1627.39,1185.62)
  SIG1 w9.84: v3(1021.65,962.6) 1187.01,962.6 v7(1189.96,959.65) ; v7(1290.35,885.83) 1328.74,885.83 v7(1349.41,865.16) ; v7(1485.24,879.92) 1576.77,879.92 v7(1585.63,888.78)
  SIG2 w6.69: v2(2208.66,688.98) v2(2262.8,749.02)
  Bottom Layer w8.66: v8(1296.26,1390.75) 1373.03,1390.75 v8(1396.65,1367.13)
  Bottom Layer w9.84: RAD_C92.2@1161.42,964.57 RAD_C92.2@1160.43,965.55 ; RAD_C141.2@1181.1,1062.99 1184.06,1060.04 1184.06,983.27 1181.1,980.32 1178.15,980.32 1175.2,977.36 1172.24,977.36 RAD_C92.2@1160.43,965.55 ; v7(1189.96,959.65) v7@1184.06,965.55 ; RAD_C138.2@1220.47,944.88 RAD_C138.2@1219.49,944.88 ; RAD_C140.2@1279.53,866.14 RAD_C140.2@1278.54,865.16 ; v7(1290.35,885.83) 1278.54,874.02 RAD_C140.2@1278.54,865.16 ; v7(1585.63,888.78) 1585.63,909.45 1621.06,944.88 RAD_C137.2@1622.05,944.88 ; RAD_C92.2@1160.43,965.55 1161.42,965.55 v7@1184.06,965.55 ; v7@1184.06,965.55 1198.82,965.55 RAD_C138.2@1219.49,944.88 ; RAD_C138.2@1219.49,944.88 1219.49,930.12 1243.11,906.5 1243.11,900.59 RAD_C140.2@1278.54,865.16
TI_1V4_APLL: RAD_C103.1 RAD_U29.H4 | length 85.1
  GND1 w7.48: v2(1519.68,1411.42) 1557.09,1441.93 v10(1576.21,1441.52)
  Bottom Layer w8.66: RAD_C103.1@1519.69,1393.7 v2(1519.68,1411.42)
TI_1V4_SYNTH: RAD_C102.1 RAD_U29.G4
  other v14: 1601.8,1441.52
TI_1V8: RAD_C5.2 RAD_C107.2 RAD_C110.1 RAD_C111.2 RAD_C112.1 RAD_C113.2 RAD_C163.2 RAD_C164.2 RAD_C165.2 RAD_C168.2 RAD_C170.2 RAD_C172.2 RAD_R47.1 RAD_R60.2 RAD_U11.8 RAD_U29.D9 RAD_U29.D18 RAD_U29.E4 RAD_U29.K17 RAD_U29.K18 RAD_U29.P1 RAD_U29.R1 RAD_U29.U18 RAD_U29.V10 | length 4442
  Top Layer w9.84: RAD_C5.2@1082.68,1181.1 1083.66,1181.1 1119.09,1181.1 1142.72,1204.72 1145.67,1204.72 1148.62,1207.68 1175.2,1207.68 1178.15,1204.72 1181.1,1204.72 1195.87,1189.96 1195.87,1175.2 1198.82,1172.24 1198.82,1163.39 1201.77,1160.43 1201.77,1157.48 1225.39,1133.86 1237.2,1133.86 RAD_C112.1@1240.16,1130.91 ; RAD_C112.1@1240.16,1131.89 RAD_C112.1@1240.16,1130.91 ; RAD_C111.2@1299.21,1023.62 RAD_C111.2@1299.21,1024.61 ; RAD_C165.2@1318.9,925.2 RAD_C165.2@1319.88,924.21 ; RAD_U29.U18@1345.89,1083.26 RAD_U29.U18@1346.46,1083.66 ; RAD_U29.R1@1397.08,1518.3 1396.65,1517.72 RAD_U29.P1@1421.57,1517.72 ; v2(1410.43,1511.81) RAD_U29.P1@1421.57,1517.72 ; RAD_C107.2@1417.32,925.2 RAD_C107.2@1417.32,924.21 ; v7(1426.18,885.83) 1429.13,882.87 1437.99,882.87 RAD_C168.2@1455.71,865.16 ; RAD_C168.2@1456.69,866.14 RAD_C168.2@1455.71,865.16 ; RAD_U29.K18@1525.03,1083.26 RAD_U29.K18@1523.62,1083.66 ; RAD_U29.K17@1525.03,1108.85 1523.62,1110.24 RAD_U29.K18@1523.62,1083.66 ; RAD_C110.1@1564.96,1003.94 1541.34,1027.56 1541.34,1039.37 1523.62,1057.09 RAD_U29.K18@1523.62,1083.66 ; v3(1591.54,859.25) 1597.44,865.16 1615.16,865.16 RAD_C163.2@1614.17,866.14 ; v3(1603.35,1033.46) 1632.87,1062.99 ; v10(1652.98,1441.52) 1653.54,1440.94 1653.54,1400.59 v7(1653.54,1378.94) 1653.54,1337.6 RAD_U29.D9@1677.17,1313.98 ; v3(1677.17,1290.35) RAD_U29.D9@1677.17,1313.98 ; RAD_U29.D18@1678.57,1083.26 1677.17,1083.66 1674.21,1080.71 1674.21,1071.85 1671.26,1068.9 1671.26,1065.94 1668.31,1062.99 1657.48,1052.17 1644.68,1052.17 1639.76,1054.13 1632.87,1061.02 1632.87,1062.99 ; RAD_U29.D9@1678.57,1313.57 RAD_U29.D9@1677.17,1313.98 ; RAD_C112.1@1240.16,1130.91 1266.24,1104.82 1299.21,1071.85 1299.21,1071.37 1299.21,1068.9 1305.12,1062.99 1311.97,1062.99 1334.65,1062.99 ; RAD_C111.2@1299.21,1024.61 1327.44,1052.83 1334.65,1060.04 1334.65,1062.99 ; RAD_C111.2@1299.21,1024.61 1313.98,1009.84 1316.93,1009.84 1322.83,1003.94 1322.83,927.17 RAD_C165.2@1319.88,924.21 ; RAD_C165.2@1319.88,924.21 1334.65,909.45 1334.65,906.5 1337.6,903.54 1340.55,903.54 1343.5,900.59 1393.7,900.59 RAD_C107.2@1417.32,924.21 ; 1334.65,1062.99 1340.55,1068.9 1340.55,1077.76 1345.97,1083.18 RAD_U29.U18@1346.46,1083.66 ; RAD_U29.U18@1346.46,1083.66 1352.36,1077.76 1352.36,1065.94 1355.32,1065.94 1358.27,1062.99 1365.16,1049.21 1374.02,1043.31 1388.78,1043.31 1425.2,1054.13 1435.04,1054.13 1439.96,1055.12 1447.83,1062.99 1514.76,1062.99 1520.67,1068.9 1520.67,1080.71 RAD_U29.K18@1523.62,1083.66 ; RAD_C107.2@1417.32,924.21 1417.32,903.54 1430.61,890.26 RAD_C168.2@1455.71,865.16 ; RAD_U29.P1@1421.57,1517.72 1423.23,1517.72 RAD_U29.P1@1422.67,1518.3 RAD_U29.P1@1421.57,1517.72 ; RAD_U29.K18@1523.62,1083.66 1524.53,1082.76 1529.53,1077.76 1529.53,1068.9 1535.43,1062.99 1632.87,1062.99
  Top Layer w15.75: v6(1266.24,1132.38) 1266.24,1104.82 1266.24,1102.85 1296.75,1072.34 1297.74,1072.34 1299.21,1071.37 1311.97,1062.99 1327.44,1052.83 v2(1330.71,1050.69)
  GND1 w15.75: v6(1259.01,1144.88) v6(1266.24,1132.38)
  GND1 w27.56: v2(1646.65,1400.59) 1646.65,1436.02 v10(1652.98,1441.52)
  SIG1 w9.84: v7(1426.18,885.83) 1435.04,876.97 v7(1435.04,853.35) ; v3(1591.54,859.25) 1597.44,853.35 v7(1635.83,853.35) ; v3(1603.35,1033.46) 1612.2,1042.32 1612.2,1219.49 1674.21,1281.5 1674.21,1287.4 v3(1677.17,1290.35) ; v7(1653.54,1378.94) 1662.4,1387.8 1815.94,1387.8 1957.68,1529.53 2140.75,1529.53 v7(2146.65,1535.43)
  GND2 w15.75: v14(1323.26,1285.03) 1323.33,1252.46 v9(1343.01,1232.78) ; v9(1378.94,1145.18) 1371.56,1152.56 1371.56,1192.91 v9(1378.94,1209.65)
  GND2 w27.56: v2(1410.43,1511.81) 1696.85,1474.41 1713.58,1457.68 1713.58,1406.5 1690.94,1383.86 1663.39,1383.86 v2(1646.65,1400.59)
  Bottom Layer w9.84: RAD_R60.2@1344.49,708.66 1343.5,708.66 1344,709.15 1375.98,741.14 1375.98,761.81 1381.89,767.72 1381.89,770.67 1384.84,773.62 1384.84,809.06 1399.61,823.82 1399.61,826.77 1402.56,829.72 1402.56,862.2 1399.61,865.16 1399.61,868.11 1384.84,882.87 1381.89,882.87 RAD_C113.2@1378.94,885.83 ; RAD_C113.2@1377.95,885.83 RAD_C113.2@1378.94,885.83 ; v7(1435.04,853.35) 1440.94,847.44 RAD_C172.2@1455.71,847.44 ; RAD_C172.2@1456.69,846.46 RAD_C172.2@1455.71,847.44 ; RAD_C164.2@1555.12,866.14 RAD_C164.2@1556.1,865.16 ; RAD_C170.2@1614.17,846.46 RAD_C170.2@1615.16,847.44 ; v7(1635.83,853.35) v7@1629.92,847.44 ; RAD_R47.1@1791.34,708.66 1792.32,708.66 1791.83,709.15 1789.37,711.61 1789.37,726.38 1721.46,794.29 1721.46,853.35 1712.6,862.2 1709.65,862.2 1706.69,865.16 1680.12,865.16 1677.17,862.2 1674.21,862.2 1659.45,847.44 v7@1629.92,847.44 ; RAD_U11.8@2071.85,1614.17 2072.83,1615.16 2043.31,1615.16 2037.4,1609.25 2037.4,1606.3 2034.45,1603.35 2034.45,1564.96 2037.4,1562.01 2037.4,1559.06 2058.07,1538.39 2143.7,1538.39 v7(2146.65,1535.43) ; RAD_C113.2@1378.94,885.83 1414.37,885.83 1420.28,879.92 1437.99,862.2 1440.94,862.2 RAD_C172.2@1455.71,847.44 ; RAD_C172.2@1455.71,847.44 1491.14,847.44 1494.09,844.49 1497.05,844.49 1500,841.54 1532.48,841.54 1535.43,844.49 1538.39,844.49 1538.39,847.44 RAD_C164.2@1556.1,865.16 ; RAD_C164.2@1556.1,865.16 1591.54,865.16 1594.49,862.2 1597.44,862.2 1600.39,859.25 1603.35,859.25 RAD_C170.2@1615.16,847.44 ; RAD_C170.2@1615.16,847.44 v7@1629.92,847.44
  Bottom Layer w15.75: v2(1330.71,1050.69) v9(1378.94,1145.18) ; v9(1343.01,1232.78) 1373.03,1216.04 v9(1378.94,1209.65)
TI_1V8_FILTERED: RAD_R60.1 RAD_R65.1 RAD_R104.2 | length 2868
  Top Layer w15.75: v12(2492.13,940.94) RAD_R104.2@2496.06,926.18
  GND1 w15.75: v2(2471.46,971.46) v12(2492.13,940.94)
  SIG2 w8.66: v2(1387.8,664.37) 1402.56,649.61 1514.76,649.61 1526.57,661.42 1635.83,661.42 1650.59,646.65 v2(2010.83,646.65) ; v2(2314.96,965.55) 2465.55,965.55 v2(2471.46,971.46)
  GND2 w15.75: v14(1053.15,1811.02) 1067.91,1721.46 1067.91,1600.39 1081.69,1586.61 1076.77,1235.24 1097.44,1214.57 1097.44,956.69 1106.3,947.83 1106.3,908.46 1085.63,887.8 1085.63,866.14 1101.38,850.39 1105.32,850.39 1133.86,821.85 1133.86,756.89 1191.93,698.82 1342.52,698.82 1385.83,742.13 v11(1446.85,742.13)
  Bottom Layer w8.66: v2(1387.8,664.37) 1387.8,682.09 1399.61,693.9 1402.56,693.9 1405.51,696.85 1411.42,696.85 1423.23,708.66 1449.8,708.66 RAD_R60.1@1450.79,708.66 ; v2(2010.83,646.65) 2270.67,906.5 2270.67,947.83 2288.39,965.55 v2(2314.96,965.55)
  Bottom Layer w15.75: v11(1446.85,742.13) RAD_R60.1@1450.79,738.39
TI_3V3: RAD_C174.2 RAD_C175.2 RAD_C176.2 RAD_C177.2 RAD_R346.2 RAD_R348.1 RAD_U12.8 RAD_U29.A13 RAD_U29.B18 RAD_U29.R18 RAD_U29.V8 RAD_U29.V15 | length 3472.6
  Top Layer w8.66: RAD_U29.A13@1755.34,1211.21 1755.91,1212.6 v8(1822.83,1212.6) ; v8(2740.16,1244.09) 2736.22,1248.03 2736.22,1251.97 2728.35,1259.84 2724.41,1259.84 2716.54,1267.72 RAD_U12.8@2716.54,1294.29 ; RAD_U12.8@2716.54,1294.29 2716.54,1295.28 RAD_U12.8@2716.54,1294.29
  Top Layer w9.84: RAD_C174.2@1141.73,1082.68 RAD_C174.2@1142.72,1083.66 ; v7(1148.62,1104.33) 1142.72,1098.43 RAD_C174.2@1142.72,1083.66 ; RAD_C176.2@1220.47,964.57 1219.49,965.55 1204.72,980.32 1201.77,980.32 1198.82,983.27 1198.82,986.22 1184.06,1000.98 1184.06,1003.94 1178.15,1009.84 1178.15,1042.32 1166.34,1054.13 1166.34,1060.04 1163.39,1062.99 1163.39,1065.94 1160.43,1065.94 RAD_C174.2@1142.72,1083.66 ; v3(1237.2,1033.46) 1231.3,1039.37 1181.1,1039.37 1175.2,1045.28 1175.2,1054.13 1145.67,1083.66 RAD_C174.2@1142.72,1083.66 ; v3(1296.26,1157.48) 1299.21,1160.43 v3@1304.13,1160.43 ; RAD_U29.V15@1320.3,1160.03 1319.88,1160.43 v3@1304.13,1160.43 ; RAD_U29.V8@1320.3,1339.16 1319.88,1340.55 1316.93,1337.6 1308.07,1337.6 1302.17,1331.69 1302.17,1328.74 1290.35,1316.93 1290.35,1174.21 1294.29,1166.34 1299.65,1163.13 v3@1304.13,1160.43 ; v2(1380.91,1062.99) RAD_U29.R18@1397.08,1083.26 ; RAD_C175.2@1712.6,885.83 1721.46,894.68 1721.46,950.79 1736.22,965.55 1736.22,968.5 1739.17,971.46 1739.17,1039.37 1733.27,1045.28 1733.27,1068.9 ; RAD_U29.B18@1729.75,1083.26 RAD_U29.B18@1730.32,1083.66 ; RAD_U29.A13@1755.34,1211.21 1753.94,1210.63 1754.35,1210.22 1756.89,1207.68 1768.7,1207.68 1774.61,1201.77 1774.61,1065.94 1769.68,1057.09 1759.84,1051.18 1750,1051.18 1745.08,1053.15 1738.19,1060.04 1736.22,1065.94 1733.27,1068.9 ; RAD_U29.B18@1730.32,1083.66 1730.32,1071.85 1733.27,1068.9 ; RAD_U29.B18@1730.32,1083.66 1733.27,1080.71 1733.27,1068.9
  PWR1 w33.46: v3(1296.26,1157.48) 1295.28,1157.48 1303.15,1165.35 1307.09,1165.35 1309.06,1167.32 ; v2(1380.91,1062.99) 1521.26,1203.15 1812.6,1203.15 v8(1822.83,1212.6) 1811.02,1200.79
  PWR2 w27.56: v3(1296.26,1157.48) v2(1380.91,1062.99)
  SIG1 w8.66: v8(1822.83,1212.6) 2098.43,1212.6 2161.42,1275.59 2354.33,1275.59 2381.89,1248.03 2688.98,1248.03 2700.79,1259.84 2728.35,1259.84 2740.16,1248.03 v8(2740.16,1244.09)
  SIG1 w9.84: v7(1071.85,1054.13) 1122.05,1104.33 v7(1148.62,1104.33) ; v3(1237.2,1033.46) 1275.59,1071.85 1275.59,1136.81 v3(1296.26,1157.48)
  Bottom Layer w9.84: RAD_R346.2@925.2,1273.62 924.21,1272.64 953.74,1243.11 953.74,1240.16 965.55,1228.35 965.55,1210.63 977.36,1198.82 977.36,1051.18 980.32,1048.23 980.32,1045.28 983.27,1042.32 983.27,1039.37 995.08,1027.56 1000.98,1027.56 RAD_R348.1@1003.94,1024.61 ; RAD_R348.1@1003.94,1023.62 RAD_R348.1@1003.94,1024.61 ; v7(1071.85,1054.13) 1077.76,1060.04 1077.76,1077.76 1080.71,1080.71 1080.71,1083.66 1083.66,1086.61 ; RAD_C177.2@1102.36,1102.36 1101.38,1101.38 1086.61,1086.61 1083.66,1086.61 ; RAD_R348.1@1003.94,1024.61 1021.65,1024.61 1083.66,1086.61
TI_3V3_VIO: C_CAN_RAD.1 C_USB_1U.1 C_USB_4U7.1 C_USB_100N.1 R_USB_RESET.1 R_USB_WAKE.1 RAD_R37.1 RAD_R38.2 RAD_R41.2 RAD_R43.2 RAD_R49.2 RAD_R106.2 RAD_R116.2 RAD_R264.2 RAD_R276.2 RAD_R277.2 RAD_R301.2 RAD_R309.2 RAD_R311.2 RAD_R346.1 RAD_R352.1 RAD_R409.2 TP_RAD_VIO.1 U_CAN_RAD.3 U_USB.6 U_USB.7 | length 7017
  Top Layer w8.66: RAD_R276.2@1200.79,2244.09 1212.6,2232.28 v3(1220.47,2232.28)
  Top Layer w9.84: RAD_R38.2@1082.68,1594.49 RAD_R38.2@1083.66,1594.49 ; v7(1092.52,1615.16) 1083.66,1606.3 RAD_R38.2@1083.66,1594.49 ; v3(1101.38,1251.97) 1113.19,1240.16 RAD_R41.2@1130.91,1240.16 ; v3(1110.24,876.97) 1116.14,882.87 1116.14,885.83 1119.09,888.78 1119.09,891.73 1142.72,915.35 TP_RAD_VIO.1@1142.72,965.55 ; v3(1122.05,1219.49) 1130.91,1228.35 RAD_R41.2@1130.91,1240.16 ; RAD_R41.2@1131.89,1240.16 RAD_R41.2@1130.91,1240.16 ; TP_RAD_VIO.1@1141.73,964.57 TP_RAD_VIO.1@1142.72,965.55 ; v7(1192.91,865.16) 1201.77,874.02 RAD_R311.2@1201.77,885.83 ; RAD_R311.2@1200.79,885.83 RAD_R311.2@1201.77,885.83 ; RAD_R43.2@1250,1259.84 RAD_R43.2@1249.02,1260.83 ; RAD_R49.2@1250,1545.28 RAD_R49.2@1249.02,1544.29 ; RAD_R264.2@1555.12,767.72 RAD_R264.2@1556.1,767.72 ; v7(1585.63,809.06) 1582.68,806.1 1529.53,806.1 1526.57,803.15 1523.62,803.15 1511.81,791.34 1497.05,791.34 1473.43,767.72 1497.05,744.09 1535.43,744.09 1541.34,750 1541.34,752.95 1555.61,767.22 RAD_R264.2@1556.1,767.72 ; v7(1641.73,806.1) 1635.83,800.2 1635.83,744.09 1626.97,735.24 1603.35,735.24 1600.39,738.19 1597.44,738.19 1588.58,747.05 1576.77,747.05 1573.82,750 1570.87,750 1564.96,755.91 1564.96,758.86 RAD_R264.2@1556.1,767.72 ; v7(1901.57,747.05) 1910.43,755.91 1910.43,767.72 RAD_R106.2@1909.45,767.72 ; RAD_R116.2@2460.63,807.09 2459.65,806.1 2486.22,806.1 v7(2489.17,809.06) ; RAD_R409.2@2598.43,1043.31 2598.43,1042.32 2610.24,1030.51 2613.19,1030.51 2616.14,1027.56 2619.09,1027.56 2619.09,1024.61 2622.05,1021.65 2622.05,1015.75 2627.95,1009.84 v3(2627.95,1006.89) ; RAD_R38.2@1083.66,1594.49 1095.47,1582.68 1095.47,1579.72 1098.43,1576.77 1098.43,1573.82 1101.38,1573.82 1104.33,1570.87 1219.49,1570.87 1228.35,1562.01 1231.3,1562.01 RAD_R49.2@1249.02,1544.29 ; RAD_R41.2@1130.91,1240.16 1145.67,1254.92 1145.67,1257.87 1151.57,1263.78 1246.06,1263.78 RAD_R43.2@1249.02,1260.83 ; TP_RAD_VIO.1@1142.72,965.55 1192.91,915.35 1192.91,894.68 1201.28,886.32 RAD_R311.2@1201.77,885.83 ; RAD_R43.2@1249.02,1260.83 1260.83,1272.64 1263.78,1272.64 1266.73,1275.59 1269.68,1275.59 1272.64,1278.54 1272.64,1476.38 1254.92,1494.09 1251.97,1494.09 RAD_R37.1@1250,1496.06 1249.02,1497.05 RAD_R49.2@1249.02,1544.29
  SIG1 w8.66: 1060.04,1783.46 1059.06,1783.46 1057.09,1783.46 1017.72,1783.46 v3(1007.87,1793.31) 1017.22,1802.66 1173.23,1958.66 1173.23,1962.6 1185.04,1974.41 1185.04,2196.85 v3(1220.47,2232.28) ; v7(1901.57,747.05) 1901.57,746.06 1897.64,750 1893.7,753.94 1889.76,753.94 1887.8,755.91 1854.33,755.91 1850.39,755.91 1848.43,757.87 1846.46,757.87 1844.49,759.84 1824.8,759.84 1818.9,753.94 1818.9,751.97 1816.93,750 1816.93,748.03 1814.96,746.06 1814.96,730.32 1816.93,728.35 1816.93,726.38 1818.9,724.41 1818.9,722.44 1820.87,720.47 1822.83,720.47 1824.8,718.5 1826.77,718.5 1828.74,716.54 1875.98,716.54 1879.92,712.6 1881.89,712.6 1883.86,710.63 1921.26,710.63 1933.07,722.44 2401.57,722.44 2440.94,761.81 2442.91,761.81 2444.88,763.78 2446.85,763.78 2452.76,769.68 2452.76,771.65 2454.72,773.62 2454.72,775.59 2488.19,809.06 v7(2489.17,809.06)
  SIG1 w9.84: v7(664.37,1960.63) 696.85,1993.11 696.85,2072.83 714.57,2090.55 717.52,2090.55 720.47,2093.5 738.19,2093.5 741.14,2090.55 744.09,2090.55 865.16,1969.49 865.16,1966.54 891.73,1939.96 891.73,1928.15 1017.22,1802.66 1033.46,1786.42 1054.13,1786.42 1057.09,1783.46 ; v3(941.93,1207.68) 980.32,1246.06 1095.47,1246.06 v3(1101.38,1251.97) ; 1059.06,1783.46 1060.04,1783.46 1062.99,1780.51 1062.99,1644.68 v7(1092.52,1615.16) ; v7(1192.91,865.16) 1228.35,829.72 1240.16,829.72 v7(1249.02,820.87) ; v7(1308.07,767.72) 1316.93,776.57 1494.09,776.57 1523.62,806.1 1582.68,806.1 v7(1585.63,809.06) ; v7(1641.73,806.1) 1662.4,785.43 1824.8,785.43 1854.33,755.91 1860.24,750 1897.64,750 1898.62,750 v7(1901.57,747.05) ; v3(2418.31,1142.72) 2604.33,1142.72 2607.28,1139.76 2666.34,1139.76 v3(2669.29,1136.81) ; v7(2489.17,809.06) 2577.76,809.06 v7(2595.47,826.77) ; v7(2625,980.32) 2627.95,983.27 v3(2627.95,1006.89)
  SIG2 w9.84: v3(1110.24,876.97) 1107.28,879.92 1107.28,995.08 1101.38,1000.98 1101.38,1021.65 1104.33,1024.61 1104.33,1027.56 1113.19,1036.42 1113.19,1210.63 v3(1122.05,1219.49)
  GND2 w6.69: v9(1619.09,1100.39) 1619.09,1123.03 v9(1621.06,1151.57) ; v9(1625,1042.32) 1625,920.28 1613.19,908.46 1613.19,837.6 v7(1641.73,806.1) ; v11(1736.22,1162.4) v9(1739.17,1197.83)
  Bottom Layer w6.69: v9(1619.09,1100.39) v9(1625,1042.32) ; v9(1621.06,1151.57) 1663.39,1193.9 v9(1739.17,1197.83) ; RAD_R309.2@1736.02,1149.41 1736.1,1154.63 v11(1736.22,1162.4)
  Bottom Layer w9.84: v7(664.37,1960.63) 679.13,1945.87 750,1945.87 752.95,1948.82 752.95,1954.72 767.22,1969 767.72,1969.49 RAD_R277.2@767.72,1968.5 ; RAD_R346.1@925.2,1167.32 924.21,1166.34 924.21,1189.96 v3(941.93,1207.68) ; v7(1249.02,820.87) 1260.83,809.06 RAD_R352.1@1260.83,788.39 ; RAD_R352.1@1259.84,787.4 RAD_R352.1@1260.83,788.39 ; v7(1308.07,767.72) 1319.88,779.53 RAD_R301.2@1319.88,788.39 ; RAD_R301.2@1318.9,787.4 RAD_R301.2@1319.88,788.39 ; U_CAN_RAD.3@2300.2,1135.83 2300.2,1136.81 2306.1,1130.91 2306.1,1116.14 2312.01,1110.24 2376.97,1110.24 C_CAN_RAD.1@2430.12,1163.39 ; v3(2418.31,1142.72) 2430.12,1154.53 C_CAN_RAD.1@2430.12,1163.39 ; C_CAN_RAD.1@2431.1,1162.2 C_CAN_RAD.1@2430.12,1163.39 ; U_USB.7@2588.58,1001.97 2589.57,1000.98 2601.38,1012.8 U_USB.6@2607.28,1012.8 ; v7(2595.47,826.77) C_USB_100N.1@2619.09,826.77 ; U_USB.6@2608.27,1013.78 U_USB.6@2607.28,1012.8 ; C_USB_100N.1@2618.11,827.56 C_USB_100N.1@2619.09,826.77 ; v7(2625,980.32) 2625,995.08 2620.57,999.51 U_USB.6@2607.28,1012.8 ; C_USB_4U7.1@2628.94,925.2 C_USB_4U7.1@2627.95,924.21 ; v3(2669.29,1136.81) 2657.48,1148.62 ; C_USB_1U.1@2696.85,1032.48 C_USB_1U.1@2695.87,1033.46 ; R_USB_WAKE.1@2775.59,1042.91 2775.59,1042.32 2766.73,1033.46 C_USB_1U.1@2695.87,1033.46 ; RAD_R352.1@1260.83,788.39 RAD_R301.2@1319.88,788.39 ; U_USB.6@2607.28,1012.8 2675.2,1012.8 C_USB_1U.1@2695.87,1033.46 ; U_USB.6@2607.28,1012.8 2607.28,944.88 C_USB_4U7.1@2627.95,924.21 ; C_USB_100N.1@2619.09,826.77 2633.86,841.54 2639.76,841.54 2642.72,844.49 2642.72,909.45 C_USB_4U7.1@2627.95,924.21 ; 2657.48,1148.62 R_USB_RESET.1@2657.48,1180.71 ; 2657.48,1148.62 2657.48,1071.85 C_USB_1U.1@2695.87,1033.46 ; R_USB_RESET.1@2657.48,1180.71 2657.48,1181.1 R_USB_RESET.1@2657.48,1180.71
TI_3V3REG_ENA: RAD_R7.2 RAD_U2.10 | length 326
  Top Layer w6.69: RAD_U2.10@777.36,1853.54 v10(777.56,1852.36)
  GND1 w6.69: v2(728.35,2143.7) 769.68,2011.81 769.68,1860.24 v10(777.56,1852.36)
  Bottom Layer w6.69: v2(728.35,2143.7) 733.36,2127.54 RAD_R7.2@735.43,2120.87
TI_3V3REG_MODE: RAD_R9.1 RAD_U2.6 | length 576.7
  Top Layer w8.66: RAD_U2.6@836.61,1736.61 836.61,1736.22 866.14,1765.75 866.14,1787.4 v3(874.02,1795.28)
  SIG2 w8.66: v3(673.23,2074.8) 708.66,2039.37 708.66,2027.56 710.63,2025.59 710.63,1966.54 783.46,1893.7 783.46,1885.83 785.43,1883.86 785.43,1872.05 787.4,1870.08 787.4,1868.11 793.31,1862.2 797.24,1862.2 799.21,1860.24 809.06,1860.24 v3(874.02,1795.28)
  Bottom Layer w8.66: v3(673.23,2074.8) 675.2,2076.77 702.76,2076.77 718.5,2092.52 734.25,2092.52 736.22,2090.55 740.16,2090.55 742.13,2088.58 744.09,2088.58 748.03,2084.65 748.03,2082.68 750,2080.71 750,2076.77 751.97,2074.8 751.97,2062.99 RAD_R9.1@767.72,2047.24
TI_3V3REG_VCC: RAD_C10.1 RAD_R9.2 RAD_U2.3 | length 570
  Top Layer w8: 777.47,1694.53 777.25,1694.75 777.25,1694.88 777.25,1715.25 777.56,1715.25 RAD_U2.3@777.56,1736.61
  Top Layer w9.84: 777.47,1694.53 776.57,1694.88 777.25,1694.88 791.34,1694.88 v7(800.2,1703.74)
  Top Layer w10: 777.47,1694.75 777.47,1694.53 RAD_C10.1@803.56,1668.44
  SIG1 w9.84: v3(729.33,2069.88) 794.29,2004.92 794.29,1990.16 817.91,1966.54 817.91,1904.53 823.82,1898.62 823.82,1895.67 826.77,1892.72 826.77,1889.76 829.72,1886.81 829.72,1824.8 847.44,1807.09 847.44,1804.13 850.39,1801.18 850.39,1783.46 847.44,1780.51 847.44,1777.56 823.82,1753.94 823.82,1727.36 v7(800.2,1703.74)
  Bottom Layer w9.84: RAD_R9.2@728.35,2047.24 729.33,2046.26 v3(729.33,2069.88)
TI_5V0: RAD_C119.1 RAD_U8.10 | length 265.3
  Top Layer w7.09: RAD_C119.1@2037.4,767.72 2081.69,812.01 2081.69,823.82 2087.6,829.72 2114.17,829.72 2117.13,832.68 2117.13,909.45 2123.03,915.35 2123.03,977.36 2125.98,980.32 RAD_U8.10@2125.98,979.82
TI_+3.3VD: RAD_C124.2 RAD_R116.1 RAD_U8.9 | length 802
  Top Layer w9.84: RAD_U8.9@2103.41,983.08 v2(2104.33,945.87) ; RAD_C124.2@2195.87,1220.47 v2(2230.32,1192.91) ; RAD_R116.1@2460.63,846.46 2494.09,854.33 2502.95,863.19 v2(2508.86,871.06)
  PWR2 w15.75: 2209.25,1078.94 2288.19,1042.52 2505.51,889.76 2508.66,883.46 v2(2508.86,871.06)
  PWR2 w33.46: v2(2104.33,945.87) 2209.25,1078.94 2209.25,1171.06 v2(2230.32,1192.91)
